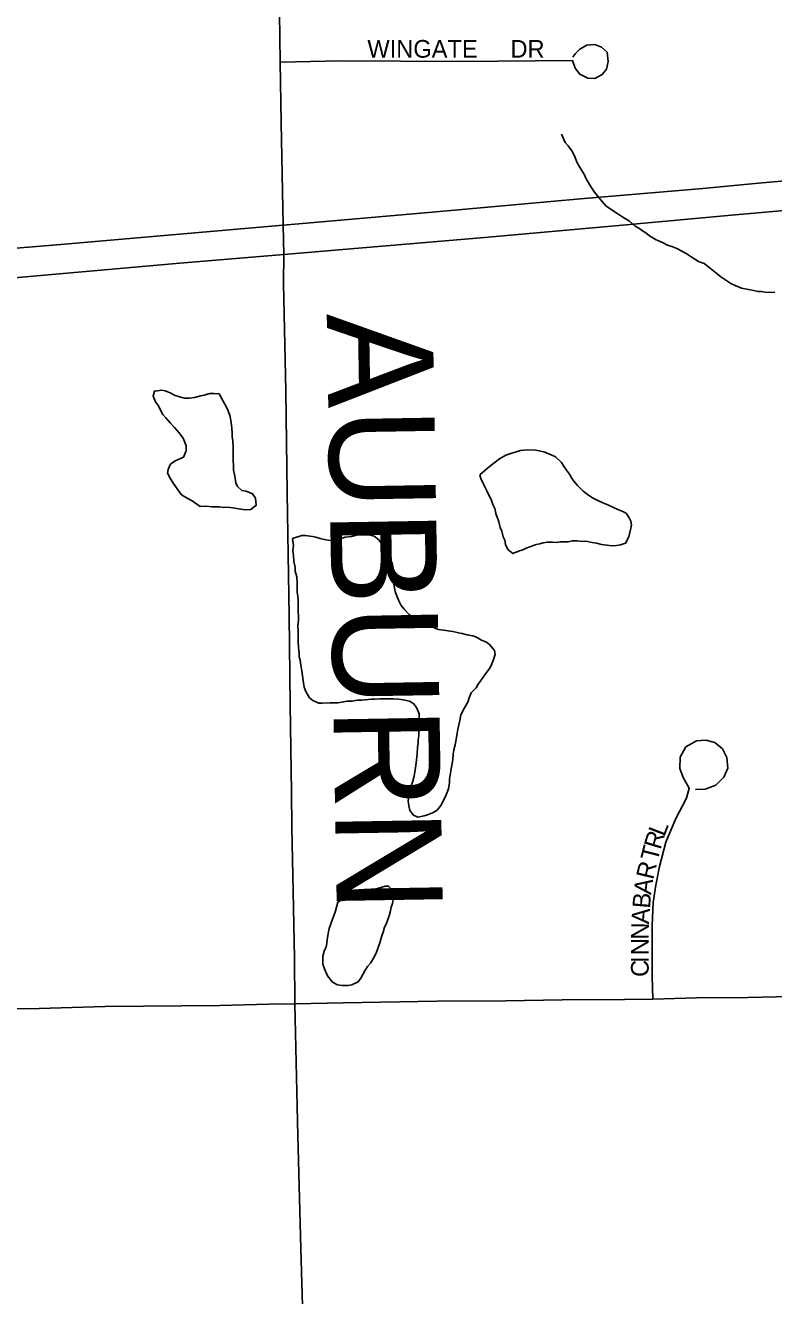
# Model space of a CAD drawing. Extents: x -10.1 to 68, y -9.5 to 29.2.
# Drawn here: x 3.483 to 3.884, y 18.737 to 19.418 of the extents above; entities that cross this region are included whole.
import ezdxf

# ---------------------------------------------------------------- set-up
doc = ezdxf.new("R2010")
doc.units = 0
for name, color, linetype in [('GM_X_County_Road', 7, 'Continuous'), ('GM_X_County_Road_Text', 7, 'Continuous'), ('GM_X_Minor_Lake', 7, 'Continuous'), ('GM_X_Minor_River', 7, 'Continuous'), ('GM_X_Township_Road', 7, 'Continuous'), ('GM_X_Township_Subdivision', 7, 'Continuous'), ('GM_X_Township_Subdivision_Text', 7, 'Continuous'), ('GM_X_US_Route', 7, 'Continuous')]:
    doc.layers.add(name, color=color, linetype=linetype)

msp = doc.modelspace()

# ---------------------------------------------------------------- linework, layer by layer
at = {"layer": 'GM_X_County_Road'}
msp.add_lwpolyline([(3.61942, 19.43824), (3.62, 19.39841), (3.62059, 19.36581), (3.62162, 19.31105), (3.62192, 19.29526), (3.6217, 19.27968), (3.62302, 19.22218), (3.62368, 19.16731), (3.62478, 19.10169), (3.62543, 19.05406), (3.62609, 19.0071), (3.62631, 18.98844), (3.62697, 18.95398), (3.62763, 18.91843), (3.62793, 18.89371), (3.62939, 18.82308), (3.63113, 18.76258), (3.63263, 18.7073)], dxfattribs=at)
at = {"layer": 'GM_X_Minor_Lake'}
for points in [[(3.55302, 19.22208), (3.55643, 19.22254), (3.55834, 19.2222), (3.56103, 19.22112), (3.56372, 19.21965), (3.56602, 19.21894), (3.5687, 19.21824), (3.57136, 19.2183), (3.57401, 19.21874), (3.57742, 19.21957), (3.57931, 19.21999), (3.58234, 19.22082), (3.58462, 19.22087), (3.58729, 19.22055), (3.58848, 19.21829), (3.58966, 19.21642), (3.59124, 19.21341), (3.59204, 19.21153), (3.59325, 19.20852), (3.5937, 19.20511), (3.59414, 19.20246), (3.5942, 19.19942), (3.59425, 19.19752), (3.59467, 19.19563), (3.59475, 19.19145), (3.5948, 19.18955), (3.59484, 19.18765), (3.59489, 19.18499), (3.59496, 19.18195), (3.59501, 19.17967), (3.59544, 19.1774), (3.59585, 19.17551), (3.59629, 19.17286), (3.59709, 19.17098), (3.59942, 19.16875), (3.60171, 19.16842), (3.60517, 19.16697), (3.60674, 19.16473), (3.6072, 19.16094), (3.6042, 19.15859), (3.60116, 19.15852), (3.59887, 19.15885), (3.59467, 19.15952), (3.59201, 19.15984), (3.58972, 19.1598), (3.58743, 19.16012), (3.58553, 19.16008), (3.58363, 19.16004), (3.5802, 19.16035), (3.57716, 19.16028), (3.57291, 19.16323), (3.57022, 19.16469), (3.56714, 19.16652), (3.56518, 19.16914), (3.56282, 19.17251), (3.56125, 19.17514), (3.55966, 19.17814), (3.56, 19.18005), (3.56109, 19.18274), (3.56371, 19.18469), (3.56559, 19.18549), (3.56823, 19.18669), (3.56968, 19.19014), (3.56962, 19.1928), (3.56881, 19.19506), (3.56801, 19.19695), (3.56567, 19.19994), (3.56333, 19.20254), (3.56099, 19.20515), (3.55865, 19.20776), (3.55709, 19.20963), (3.5559, 19.21189), (3.55471, 19.21414), (3.55314, 19.21639), (3.55194, 19.2194), (3.55264, 19.22208), (3.55302, 19.22208)], [(3.55302, 19.22208), (3.55264, 19.22208), (3.55194, 19.2194), (3.55314, 19.21639), (3.55471, 19.21414), (3.5559, 19.21189), (3.55709, 19.20963), (3.55865, 19.20776), (3.56099, 19.20515), (3.56333, 19.20254), (3.56567, 19.19994), (3.56801, 19.19695), (3.56881, 19.19506), (3.56962, 19.1928), (3.56968, 19.19014), (3.56823, 19.18669), (3.56559, 19.18549), (3.56371, 19.18469), (3.56109, 19.18274), (3.56, 19.18005), (3.55966, 19.17814), (3.56125, 19.17514), (3.56282, 19.17251), (3.56518, 19.16914), (3.56714, 19.16652), (3.57022, 19.16469), (3.57291, 19.16323), (3.57716, 19.16028), (3.5802, 19.16035), (3.58363, 19.16004), (3.58553, 19.16008), (3.58743, 19.16012), (3.58972, 19.1598), (3.59201, 19.15984), (3.59467, 19.15952), (3.59887, 19.15885), (3.60116, 19.15852), (3.6042, 19.15859), (3.6072, 19.16094)], [(3.6072, 19.16094), (3.60674, 19.16473), (3.60517, 19.16697), (3.60171, 19.16842), (3.59942, 19.16875), (3.59709, 19.17098), (3.59629, 19.17286), (3.59585, 19.17551), (3.59544, 19.1774), (3.59501, 19.17967), (3.59496, 19.18195), (3.59489, 19.18499), (3.59484, 19.18765), (3.5948, 19.18955), (3.59475, 19.19145), (3.59467, 19.19563), (3.59425, 19.19752), (3.5942, 19.19942), (3.59414, 19.20246), (3.5937, 19.20511), (3.59325, 19.20852), (3.59204, 19.21153), (3.59124, 19.21341), (3.58966, 19.21642), (3.58848, 19.21829), (3.58729, 19.22055), (3.58462, 19.22087), (3.58234, 19.22082), (3.57931, 19.21999), (3.57742, 19.21957), (3.57401, 19.21874), (3.57136, 19.2183), (3.5687, 19.21824), (3.56602, 19.21894), (3.56372, 19.21965), (3.56103, 19.22112), (3.55834, 19.2222), (3.55643, 19.22254), (3.55302, 19.22208)], [(3.79748, 19.13922), (3.80014, 19.13928), (3.80242, 19.13971), (3.80506, 19.14053), (3.80689, 19.14399), (3.80793, 19.14857), (3.80827, 19.15048), (3.80785, 19.15237), (3.80705, 19.15426), (3.80548, 19.1565), (3.80356, 19.1576), (3.80087, 19.15868), (3.79856, 19.15977), (3.79549, 19.16122), (3.7928, 19.1623), (3.79012, 19.16339), (3.78742, 19.16485), (3.78511, 19.16632), (3.7824, 19.16854), (3.77929, 19.17151), (3.77735, 19.17375), (3.77616, 19.17563), (3.77498, 19.1775), (3.77341, 19.17975), (3.77185, 19.18199), (3.77066, 19.18387), (3.76756, 19.18684), (3.76525, 19.18793), (3.76179, 19.18937), (3.75874, 19.19007), (3.75683, 19.19041), (3.75226, 19.19069), (3.74885, 19.19023), (3.74582, 19.18941), (3.74355, 19.1886), (3.74091, 19.18778), (3.73753, 19.18581), (3.73453, 19.18346), (3.73191, 19.18151), (3.72967, 19.17956), (3.72706, 19.17722)], [(3.72706, 19.17722), (3.72748, 19.17533), (3.72907, 19.17194), (3.73067, 19.16856), (3.73186, 19.1663), (3.73304, 19.16405), (3.73386, 19.1614), (3.73505, 19.15915), (3.73549, 19.1565), (3.73629, 19.15462), (3.7371, 19.15197), (3.73793, 19.14895), (3.73873, 19.14707), (3.73956, 19.14405), (3.74036, 19.14217), (3.74079, 19.1399), (3.74199, 19.13726), (3.74469, 19.13504), (3.74771, 19.13624), (3.74998, 19.13705), (3.75186, 19.13786), (3.75375, 19.13866), (3.75714, 19.13987), (3.75904, 19.14029), (3.76093, 19.14071), (3.7632, 19.14114), (3.76586, 19.1412), (3.76816, 19.14087), (3.77005, 19.14129), (3.77195, 19.14133), (3.77423, 19.14138), (3.7765, 19.14181), (3.77916, 19.14187), (3.78183, 19.14154), (3.78374, 19.14159), (3.78717, 19.1409), (3.78946, 19.14057), (3.79214, 19.13987), (3.79519, 19.13955), (3.79748, 19.13922), (3.80014, 19.13928), (3.80242, 19.13971), (3.80506, 19.14053), (3.80689, 19.14399), (3.80793, 19.14857), (3.80827, 19.15048), (3.80785, 19.15237), (3.80705, 19.15426), (3.80548, 19.1565), (3.80356, 19.1576), (3.80087, 19.15868), (3.79856, 19.15977), (3.79549, 19.16122), (3.7928, 19.1623), (3.79012, 19.16339), (3.78742, 19.16485), (3.78511, 19.16632), (3.7824, 19.16854), (3.77929, 19.17151), (3.77735, 19.17375), (3.77616, 19.17563), (3.77498, 19.1775), (3.77341, 19.17975), (3.77185, 19.18199), (3.77066, 19.18387), (3.76756, 19.18684), (3.76525, 19.18793), (3.76179, 19.18937), (3.75874, 19.19007), (3.75683, 19.19041), (3.75226, 19.19069), (3.74885, 19.19023), (3.74582, 19.18941), (3.74355, 19.1886), (3.74091, 19.18778), (3.73753, 19.18581), (3.73453, 19.18346), (3.73191, 19.18151), (3.72967, 19.17956), (3.72706, 19.17722)], [(3.72706, 19.17722), (3.72748, 19.17533), (3.72907, 19.17194), (3.73067, 19.16856), (3.73186, 19.1663), (3.73304, 19.16405), (3.73386, 19.1614), (3.73505, 19.15915), (3.73549, 19.1565), (3.73629, 19.15462), (3.7371, 19.15197), (3.73793, 19.14895), (3.73873, 19.14707), (3.73956, 19.14405), (3.74036, 19.14217), (3.74079, 19.1399), (3.74199, 19.13726), (3.74469, 19.13504), (3.74771, 19.13624), (3.74998, 19.13705), (3.75186, 19.13786), (3.75375, 19.13866), (3.75714, 19.13987), (3.75904, 19.14029), (3.76093, 19.14071), (3.7632, 19.14114), (3.76586, 19.1412), (3.76816, 19.14087), (3.77005, 19.14129), (3.77195, 19.14133), (3.77423, 19.14138), (3.7765, 19.14181), (3.77916, 19.14187), (3.78183, 19.14154), (3.78374, 19.14159), (3.78717, 19.1409), (3.78946, 19.14057), (3.79214, 19.13987), (3.79519, 19.13955), (3.79748, 19.13922)], [(3.71617, 19.04549), (3.71687, 19.04855), (3.71868, 19.05239), (3.72052, 19.05547), (3.72123, 19.05776), (3.72232, 19.06045), (3.72492, 19.06316), (3.72602, 19.06509), (3.7275, 19.06702), (3.73009, 19.0705), (3.73231, 19.07358), (3.7334, 19.07589), (3.73412, 19.0778), (3.7352, 19.08087), (3.73477, 19.08314), (3.73242, 19.08613), (3.73049, 19.08761), (3.7278, 19.08869), (3.72511, 19.09015), (3.72319, 19.09087), (3.72013, 19.09156), (3.71745, 19.09226), (3.71555, 19.0926), (3.71249, 19.0933), (3.70753, 19.09395), (3.70486, 19.09427), (3.70294, 19.09499), (3.70063, 19.09646), (3.69872, 19.0968), (3.69641, 19.09789), (3.69334, 19.09934), (3.69103, 19.10081), (3.68909, 19.10229), (3.68637, 19.10527), (3.6848, 19.10714), (3.68361, 19.10977), (3.6824, 19.11278), (3.6816, 19.11467), (3.68118, 19.11656), (3.68073, 19.11997), (3.68066, 19.12301), (3.68062, 19.12491), (3.68057, 19.12719), (3.68015, 19.12908), (3.67934, 19.13172), (3.67814, 19.13435), (3.67616, 19.13773), (3.67498, 19.13961), (3.67264, 19.14259), (3.67031, 19.14444), (3.66764, 19.14515), (3.6646, 19.14508), (3.66155, 19.14501), (3.65815, 19.14418), (3.65473, 19.14373), (3.65209, 19.14291), (3.64982, 19.14248), (3.64716, 19.14204), (3.64449, 19.14236), (3.64143, 19.14306), (3.63914, 19.14377), (3.63723, 19.14411), (3.63341, 19.14478), (3.63151, 19.14474), (3.6266, 19.14311)], [(3.6266, 19.14311), (3.62706, 19.13933), (3.62674, 19.13666), (3.62717, 19.13401), (3.62724, 19.13097), (3.62807, 19.12756), (3.62811, 19.12567), (3.62894, 19.12264), (3.62901, 19.11922), (3.62905, 19.11733), (3.62911, 19.11429), (3.62954, 19.11201), (3.62958, 19.11012), (3.62963, 19.10784), (3.62968, 19.10556), (3.62972, 19.10366), (3.62976, 19.10176), (3.62981, 19.09948), (3.6295, 19.09605), (3.62955, 19.09377), (3.62962, 19.09074), (3.62968, 19.0877), (3.62974, 19.08466), (3.63019, 19.08163), (3.63023, 19.07973), (3.63065, 19.07784), (3.63109, 19.07519), (3.63153, 19.07215), (3.63197, 19.06951), (3.63243, 19.06572), (3.63286, 19.06344), (3.63367, 19.06118), (3.63564, 19.0578), (3.63757, 19.05633), (3.64065, 19.05487), (3.64255, 19.05491), (3.64673, 19.055), (3.64902, 19.05505), (3.65092, 19.0551), (3.65395, 19.05554), (3.65584, 19.05596), (3.6585, 19.05602), (3.66116, 19.05646), (3.66382, 19.05652), (3.66572, 19.05656), (3.66875, 19.057), (3.67066, 19.05704), (3.67332, 19.0571), (3.67598, 19.05716), (3.67826, 19.05721), (3.68054, 19.05726), (3.68359, 19.05695), (3.68588, 19.05661), (3.68932, 19.05593), (3.69163, 19.05446), (3.6932, 19.05221), (3.69441, 19.0492), (3.69445, 19.0473), (3.69451, 19.04426), (3.69457, 19.0416), (3.69424, 19.03931), (3.69428, 19.03742), (3.69395, 19.03513), (3.69399, 19.03323), (3.69365, 19.03132), (3.69335, 19.02751), (3.69303, 19.02447), (3.69272, 19.02142), (3.69238, 19.01913), (3.6917, 19.0157), (3.69099, 19.01302), (3.68992, 19.00996), (3.68958, 19.00805), (3.68887, 19.00576), (3.68856, 19.00233), (3.68899, 19.00006), (3.68942, 18.99741), (3.69138, 18.99479), (3.69369, 18.9937), (3.69709, 18.99453), (3.69899, 18.99495), (3.70162, 18.99615), (3.70388, 18.99734), (3.70611, 19.00005), (3.70757, 19.00274), (3.70902, 19.00581), (3.7101, 19.00888), (3.71079, 19.01231), (3.71075, 19.01421), (3.71142, 19.01841), (3.71175, 19.02069), (3.71243, 19.02451), (3.71275, 19.02756), (3.71308, 19.02984), (3.71378, 19.03252), (3.71412, 19.03443), (3.71445, 19.03671), (3.71479, 19.03862), (3.71513, 19.04091), (3.71617, 19.04549)], [(3.67331, 18.92636), (3.6745, 18.9302), (3.67522, 18.93211), (3.67592, 18.93479), (3.67702, 18.93671), (3.67774, 18.93901), (3.67845, 18.94092), (3.67916, 18.9436), (3.6795, 18.94551), (3.68022, 18.94742), (3.68055, 18.94971), (3.68049, 18.95237), (3.68006, 18.95464), (3.67812, 18.95688), (3.67621, 18.95684), (3.67395, 18.95603), (3.67092, 18.9552), (3.66829, 18.954), (3.66489, 18.95279), (3.66224, 18.95197), (3.66035, 18.95155), (3.65695, 18.95034), (3.65393, 18.94951), (3.65317, 18.94911), (3.65279, 18.94949)], [(3.65279, 18.94949), (3.65091, 18.9483), (3.6495, 18.94295), (3.64806, 18.93912), (3.64699, 18.93606), (3.64627, 18.93415), (3.64593, 18.93224), (3.64559, 18.93033), (3.64525, 18.92804), (3.64492, 18.92613), (3.64457, 18.92423), (3.64348, 18.92192), (3.64278, 18.91925), (3.64283, 18.91697), (3.64287, 18.91507), (3.64369, 18.91243), (3.64529, 18.90866), (3.64802, 18.9053), (3.65071, 18.90384), (3.65338, 18.90352), (3.65643, 18.90358), (3.65832, 18.904), (3.66171, 18.9056), (3.66319, 18.90753), (3.66429, 18.90945), (3.66539, 18.91138), (3.66686, 18.91369), (3.66834, 18.91562), (3.67055, 18.91909), (3.67164, 18.92139), (3.67236, 18.92331), (3.67331, 18.92636)]]:
    msp.add_lwpolyline(points, dxfattribs=at)
at = {"layer": 'GM_X_Minor_River'}
msp.add_lwpolyline([(3.77072, 19.35982), (3.77272, 19.35531), (3.77428, 19.35344), (3.77624, 19.35082), (3.77782, 19.34782), (3.77903, 19.3448), (3.78022, 19.34255), (3.78179, 19.33992), (3.78297, 19.33805), (3.78377, 19.33617), (3.78575, 19.33279), (3.78693, 19.33091), (3.7885, 19.32867), (3.79006, 19.3268), (3.79241, 19.32381), (3.79474, 19.3212), (3.80092, 19.31715), (3.80362, 19.31531), (3.80709, 19.31311), (3.81019, 19.31052), (3.81211, 19.30942), (3.81405, 19.30794), (3.81597, 19.30684), (3.81791, 19.30536), (3.82138, 19.30316), (3.8233, 19.30244), (3.8256, 19.30135), (3.82752, 19.30025), (3.82982, 19.29954), (3.83251, 19.29846), (3.8352, 19.297), (3.83751, 19.29591), (3.84021, 19.29407), (3.84407, 19.29149), (3.84714, 19.29042), (3.85061, 19.28783), (3.85332, 19.28561), (3.85603, 19.28339), (3.85874, 19.28155), (3.86144, 19.27971), (3.86374, 19.27862), (3.8672, 19.27717), (3.87102, 19.27649), (3.87293, 19.27615), (3.87598, 19.27546), (3.87788, 19.2755), (3.87979, 19.27516), (3.88513, 19.2749)], dxfattribs=at)
at = {"layer": 'GM_X_Township_Road'}
msp.add_lwpolyline([(3.45561, 18.89088), (3.49094, 18.89131), (3.52628, 18.8924), (3.58758, 18.89284), (3.61397, 18.89349), (3.62793, 18.89371), (3.65375, 18.89429), (3.704, 18.89517), (3.74088, 18.89539), (3.77116, 18.89582), (3.80452, 18.89604), (3.81967, 18.89626), (3.84315, 18.89692), (3.87058, 18.89714), (3.90877, 18.89802), (3.94081, 18.89824), (3.98142, 18.89912), (4.01785, 18.89956), (4.04023, 18.89978), (4.1011, 18.90044), (4.19251, 18.90156), (4.29113, 18.90314), (4.39448, 18.90471)], dxfattribs=at)
at = {"layer": 'GM_X_Township_Subdivision'}
for points in [[(3.62, 19.39841), (3.65241, 19.399), (3.71644, 19.3988), (3.77657, 19.3992), (3.77813, 19.3951), (3.78047, 19.39197), (3.78477, 19.38982), (3.78867, 19.38963), (3.79258, 19.39178), (3.79479, 19.39465), (3.7957, 19.3988), (3.79512, 19.40369), (3.79219, 19.40642), (3.78867, 19.40778), (3.78438, 19.40739), (3.78047, 19.40525), (3.77813, 19.4029), (3.77676, 19.40095)], [(3.81967, 18.89626), (3.81923, 18.90855), (3.81923, 18.93577), (3.81989, 18.94806), (3.8212, 18.95728), (3.82318, 18.96737), (3.82669, 18.98032), (3.83196, 18.99305), (3.83766, 19.00402), (3.8392, 19.00929), (3.83591, 19.015), (3.83415, 19.01983), (3.83437, 19.02597), (3.83744, 19.03146), (3.84315, 19.03475), (3.84798, 19.03497), (3.85281, 19.03387), (3.85698, 19.03036), (3.85939, 19.02575), (3.85983, 19.02005), (3.85763, 19.01522), (3.85346, 19.01083), (3.84776, 19.00885), (3.84249, 19.00863)]]:
    msp.add_lwpolyline(points, dxfattribs=at)
at = {"layer": 'GM_X_US_Route'}
for points in [[(3.29415, 19.27871), (3.31772, 19.28242), (3.3578, 19.28735), (3.42382, 19.29421), (3.50034, 19.30042), (3.62162, 19.31105), (3.63002, 19.31178), (3.7014, 19.318), (3.78093, 19.32507), (3.84652, 19.33064), (3.87631, 19.33343), (4.07094, 19.35058), (4.1121, 19.35444), (4.25507, 19.3673), (4.31187, 19.37244), (4.37511, 19.37694)], [(3.29667, 19.26288), (3.33336, 19.26827), (3.40217, 19.27663), (3.4221, 19.27834), (3.4654, 19.28177), (3.56615, 19.29056), (3.62192, 19.29526), (3.72948, 19.30449), (3.8015, 19.31092), (3.86174, 19.31628), (4.01521, 19.33), (4.10288, 19.33815), (4.14125, 19.34158), (4.19591, 19.34651), (4.29172, 19.35508), (4.35389, 19.36001), (4.39161, 19.36215)]]:
    msp.add_lwpolyline(points, dxfattribs=at)

# ---------------------------------------------------------------- texts
at = {"layer": 'GM_X_County_Road_Text'}
msp.add_text('AUBURN', height=0.056818, rotation=270.96883, dxfattribs=at).set_placement((3.64493, 19.26345))
at = {"layer": 'GM_X_Township_Subdivision_Text'}
for s, rotation, p in [('WINGATE', 0.00001, (3.66672, 19.40076)), ('DR', 0.00001, (3.74339, 19.40075)), ('R', 73.27749, (3.82374, 18.97598)), ('L', 68.98994, (3.82584, 18.98299)), ('T', 75.81133, (3.82214, 18.96963)), ('R', 76.57037, (3.81979, 18.95994)), ('A', 82.23778, (3.81871, 18.95193)), ('B', 85.40574, (3.81813, 18.94459)), ('A', 86.21645, (3.81758, 18.93631)), ('N', 89.10379, (3.81745, 18.9281)), ('N', 89.95627, (3.81745, 18.91981)), ('C', 89.95142, (3.81744, 18.90814)), ('I', 89.95725, (3.81744, 18.91564))]:
    msp.add_text(s, height=0.00947, rotation=rotation, dxfattribs=at).set_placement(p)

doc.saveas('drawing.dxf')
